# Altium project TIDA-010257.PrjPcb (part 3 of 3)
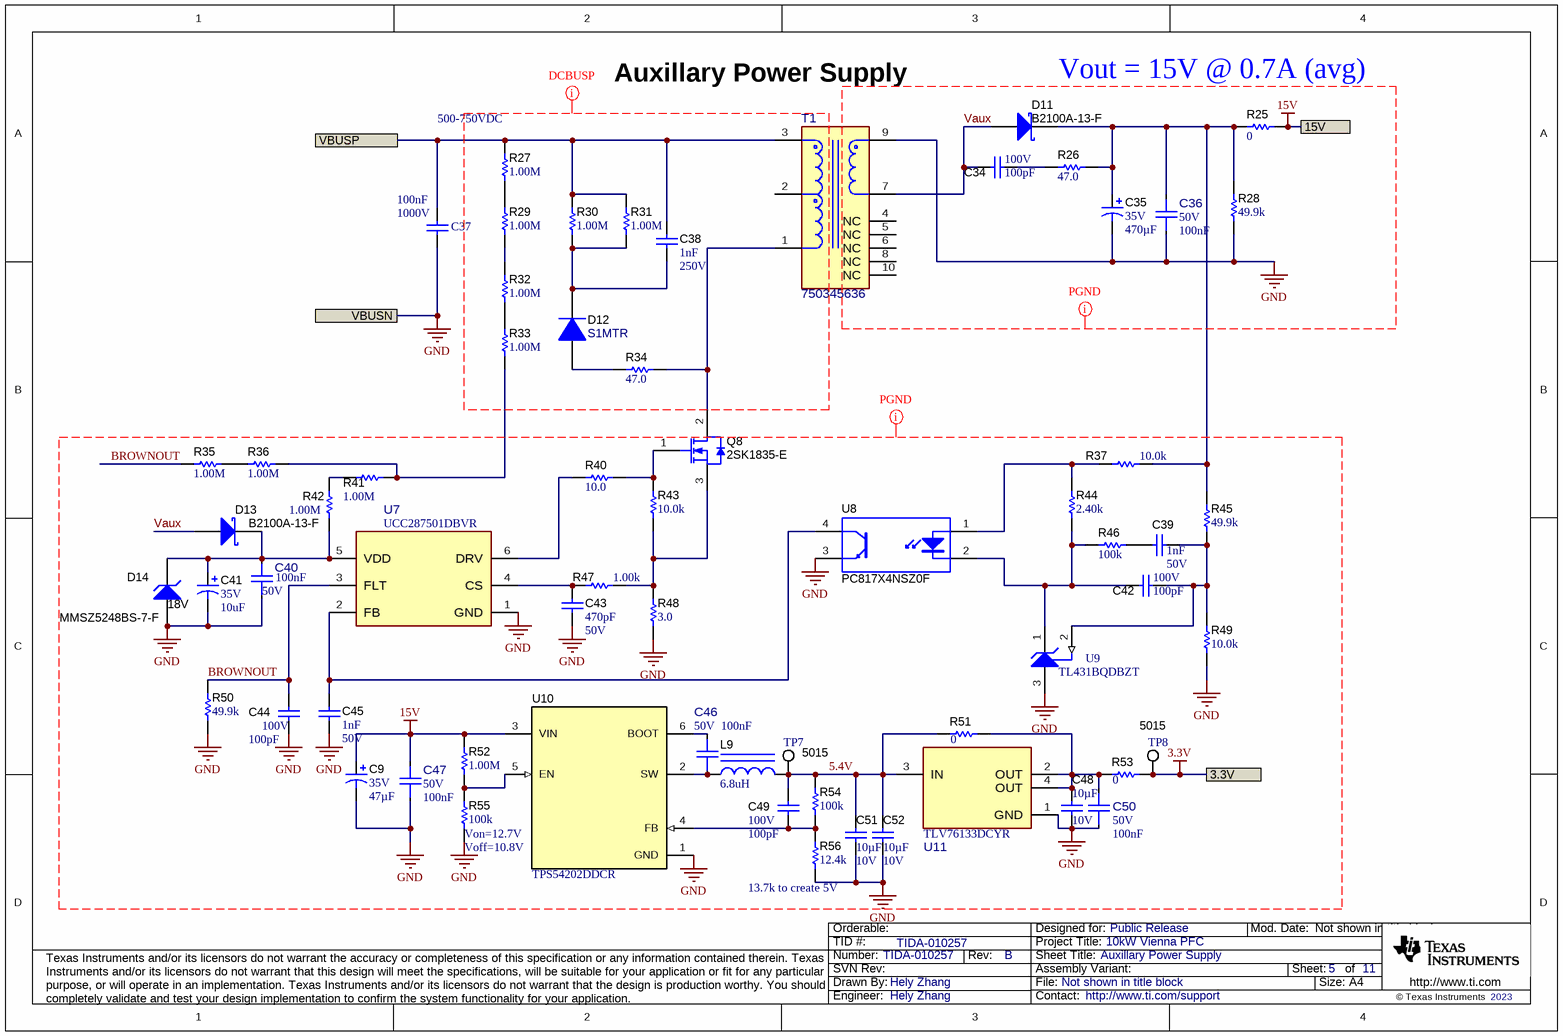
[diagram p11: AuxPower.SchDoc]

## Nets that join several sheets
3.3V: PowerStage (9 pins), GateDrivers (9 pins), InputVoltageSensing (14 pins), OutputVoltageSensing (12 pins), Controller (15 pins), AuxPower (R53.1 TP8.1)
3.3V_ACSensing: IsolatedPower (R75.1 TP13.1), InputVoltageSensing (9 pins)
3.3V_DCSensing: IsolatedPower (R58.1 TP9.1), OutputVoltageSensing (6 pins)
5V_ISO: Main (J9.1), Controller (C142.1 U26.8)
15V: Main (D1.1), IsolatedPower (8 pins), EMCInputFilter (D3.2), AuxPower (5 pins)
15V_GateA: GateDrivers (C126.2 C127.1 U23.5), IsolatedPower (R61.1)
15V_GateB: GateDrivers (C137.2 C138.1 U25.5), IsolatedPower (R67.1)
15V_GateC: GateDrivers (C134.2 C135.1 U24.5), IsolatedPower (R64.1)
EGND: Main (J7.1), EMCInputFilter (C7.2 C8.2 GD1.1)
GND_ACSensing: IsolatedPower (6 pins), InputVoltageSensing (15 pins)
GND_GATEA: PowerStage (Q2.3 Q3.3), GateDrivers (C126.1 C127.2 R159.2 U23.8), IsolatedPower (5 pins)
GND_GATEB: PowerStage (Q4.3 Q5.3), GateDrivers (C137.1 C138.2 R161.2 U25.8), IsolatedPower (5 pins)
GND_GATEC: PowerStage (Q6.3 Q7.3), GateDrivers (C134.1 C135.2 R160.2 U24.8), IsolatedPower (5 pins)
GND_ISO: Main (J9.4), Controller (C142.2 U26.5)
VBUSM: Main (J6.1), PowerStage (16 pins), IsolatedPower (6 pins), EMCInputFilter (C10.2), OutputVoltageSensing (10 pins)
VBUSN: Main (J8.1 J10.2 J10.3), PowerStage (28 pins), GateDrivers (15 pins), IsolatedPower (8 pins), EMCInputFilter (Q1.2 R2.2), InputVoltageSensing (22 pins), OutputVoltageSensing (15 pins), Controller (29 pins), AuxPower (27 pins)
#GD_ENABLE: GateDrivers (R137.2 R142.2 R143.2), Controller (U27.43)
IA_AD: PowerStage (C12.1 R13.1), Controller (U27.15)
IB_AD: PowerStage (C17.1 R15.1), Controller (U27.21)
IC_AD: PowerStage (C21.1 R18.1), Controller (U27.8)
PWMA: GateDrivers (R135.2 TP19.1), Controller (R155.2 U27.38)
PWMB: GateDrivers (R140.2 TP21.1), Controller (U27.40)
PWMC: GateDrivers (R138.2 TP20.1), Controller (U27.48)
QA_GATE: PowerStage (Q2.1 Q3.1), GateDrivers (R136.2 R159.1 U23.7)
QB_GATE: PowerStage (Q4.1 Q5.1), GateDrivers (R141.2 R161.1 U25.7)
QC_GATE: PowerStage (Q6.1 Q7.1), GateDrivers (R139.2 R160.1 U24.7)
RELAY: EMCInputFilter (R1.2), Controller (U27.26)
RX: Main (J9.2), Controller (R147.2)
TMPA: PowerStage (C28.1 R22.1), Controller (U27.6)
TMPB: PowerStage (C29.1 R23.1), Controller (U27.5)
TMPC: PowerStage (C30.1 R24.1), Controller (U27.14)
TX: Main (J9.3), Controller (R148.2)
V_A: PowerStage (L4.1), EMCInputFilter (K1.2), InputVoltageSensing (R80.1)
V_B: PowerStage (L5.1), EMCInputFilter (K2.2 RT1.2), InputVoltageSensing (R91.1)
V_BUSN_AD: OutputVoltageSensing (C121.2 R130.2), Controller (U27.11)
V_BUSP_AD: OutputVoltageSensing (C112.2 R119.2), Controller (U27.9)
V_C: PowerStage (L7.1), EMCInputFilter (L2.6), InputVoltageSensing (R104.1)
V_L1: Main (J1.1), EMCInputFilter (F1.1)
V_L2: Main (J2.1), EMCInputFilter (F2.1)
V_L3: Main (J3.1), EMCInputFilter (F3.1)
VA_AD: InputVoltageSensing (C85.2 R85.1), Controller (U27.20)
VB_AD: InputVoltageSensing (C95.2 R98.1), Controller (U27.23)
VBUSP: Main (J4.1), PowerStage (10 pins), OutputVoltageSensing (R114.1), AuxPower (6 pins)
VC_AD: InputVoltageSensing (C104.2 R109.1), Controller (U27.24)
VN: Main (J5.1), EMCInputFilter (16 pins)

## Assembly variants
001: not fitted C10 C34 C57 C58 C65 C69 C72 C73 C83 C92 C102 C111 C120 FID1 FID2 FID3 FID4 FID5 FID6 R12 R51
